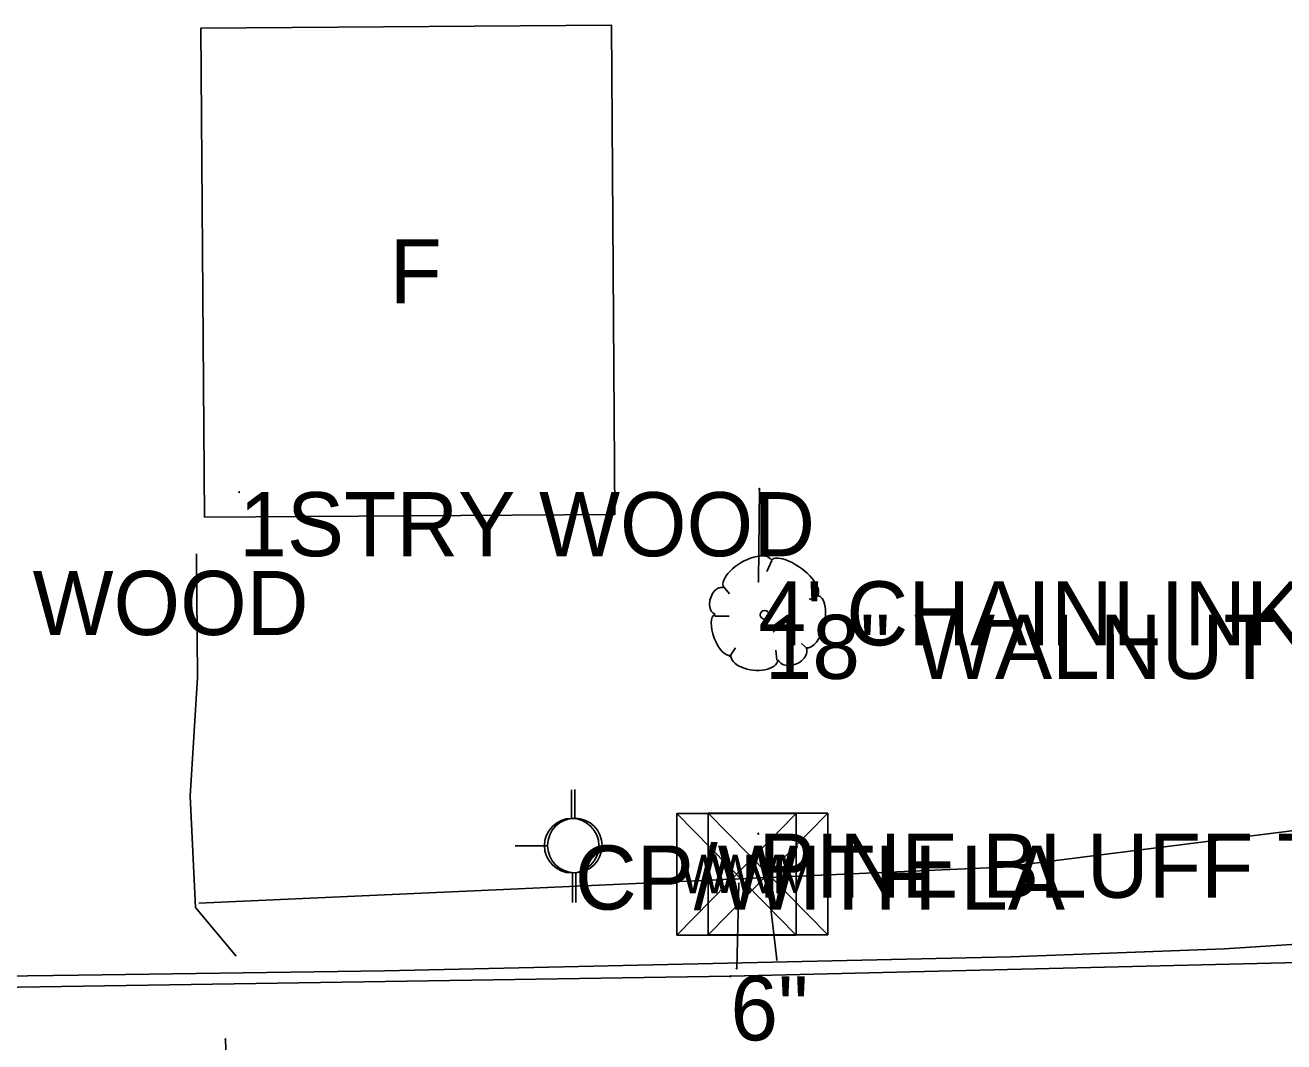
# Model space of a CAD drawing. Extents: x 1304270 to 1306561, y 1876019 to 1876752.
# Drawn here: x 1305717.8 to 1305816.1, y 1876418.6 to 1876497.9 of the extents above; entities that cross this region are included whole.
import ezdxf

# ---------------------------------------------------------------- set-up
doc = ezdxf.new("R2010")
doc.units = 0
for name, color, linetype in [('S_BUILDING', 7, 'Continuous'), ('S_BUILDING_ANNOT', 7, 'Continuous'), ('S_DRIVEWAY', 7, 'Continuous'), ('S_EDGE_PAVEMENT', 7, 'Continuous'), ('S_FENCE', 7, 'Continuous'), ('S_FENCE_ANNOT', 7, 'Continuous'), ('S_MISC_STRUCTURES_ANNOT', 7, 'Continuous'), ('S_MSC_PT_SYM', 7, 'Continuous'), ('S_SHOULDER', 7, 'Continuous'), ('S_STR_PT_SYM', 7, 'Continuous'), ('S_TREE', 7, 'Continuous'), ('S_TREE_ANNOT', 7, 'Continuous'), ('S_UTILITY_POLE', 7, 'Continuous'), ('S_UTILITY_POLE_ANNOT', 7, 'Continuous'), ('S_UTL_PT_SYM', 7, 'Continuous'), ('S_WATER_UTILITIES', 7, 'Continuous'), ('S_WATER_UTILITIES_ANNOT', 7, 'Continuous')]:
    doc.layers.add(name, color=color, linetype=linetype)

msp = doc.modelspace()

# ---------------------------------------------------------------- linework, layer by layer
at = {"layer": 'S_BUILDING'}
msp.add_lwpolyline([(1305731.787, 1876459.522), (1305731.52, 1876497.69), (1305763.568, 1876497.915), (1305763.835, 1876459.747)], close=True, dxfattribs=at)
at = {"layer": 'S_DRIVEWAY'}
msp.add_lwpolyline([(1305731.158, 1876456.665), (1305731.238, 1876447.016), (1305730.683, 1876437.757), (1305731.088, 1876429.064), (1305734.272, 1876425.27)], dxfattribs=at)
at = {"layer": 'S_EDGE_PAVEMENT'}
msp.add_lwpolyline([(1305650.553, 1876423.213), (1305674.323, 1876423.347), (1305698.094, 1876423.481), (1305721.971, 1876423.799), (1305745.849, 1876424.117), (1305770.295, 1876424.671), (1305794.741, 1876425.225), (1305811.419, 1876425.847), (1305825.074, 1876426.721), (1305843.965, 1876426.778), (1305860.029, 1876426.977), (1305876.093, 1876427.175), (1305883.239, 1876427.589), (1305898.065, 1876427.364), (1305904.047, 1876427.054), (1305918.225, 1876426.762), (1305933.321, 1876426.775)], dxfattribs=at)
at = {"layer": 'S_FENCE'}
msp.add_line((1305775.045, 1876454.521), (1305775.108, 1876461.735), dxfattribs=at)
msp.add_lwpolyline([(1305775.045, 1876454.521), (1305775.108, 1876461.735)], dxfattribs=at)
msp.add_lwpolyline([(1305775.045, 1876454.521), (1305775.108, 1876461.735)], dxfattribs=at)
at = {"layer": 'S_MSC_PT_SYM'}
for points in [[(1305775.108, 1876461.735), (1305775.108, 1876461.785), (1305775.108, 1876461.735), (1305775.058, 1876461.735), (1305775.108, 1876461.735), (1305775.108, 1876461.685), (1305775.108, 1876461.735), (1305775.158, 1876461.735)], [(1305775.045, 1876454.521), (1305775.045, 1876454.571), (1305775.045, 1876454.521), (1305774.995, 1876454.521), (1305775.045, 1876454.521), (1305775.045, 1876454.471), (1305775.045, 1876454.521), (1305775.095, 1876454.521)], [(1305775.032, 1876434.828), (1305775.032, 1876434.878), (1305775.032, 1876434.828), (1305774.982, 1876434.828), (1305775.032, 1876434.828), (1305775.032, 1876434.778), (1305775.032, 1876434.828), (1305775.082, 1876434.828)]]:
    msp.add_lwpolyline(points, dxfattribs=at)
at = {"layer": 'S_SHOULDER'}
msp.add_lwpolyline([(1305731.365, 1876429.405), (1305755.145, 1876430.481), (1305774.628, 1876431.347), (1305794.112, 1876432.214), (1305818.312, 1876435.261), (1305824.037, 1876438.54)], dxfattribs=at)
at = {"layer": 'S_STR_PT_SYM'}
msp.add_lwpolyline([(1305734.507, 1876461.478), (1305734.507, 1876461.528), (1305734.507, 1876461.478), (1305734.457, 1876461.478), (1305734.507, 1876461.478), (1305734.507, 1876461.428), (1305734.507, 1876461.478), (1305734.557, 1876461.478)], dxfattribs=at)
at = {"layer": 'S_TREE'}
for p, q in [((1305776.083, 1876456.152), (1305775.696, 1876455.299)), ((1305772.286, 1876454.137), (1305772.789, 1876453.556)), ((1305779.648, 1876453.362), (1305778.989, 1876453.091)), ((1305771.627, 1876451.812), (1305772.751, 1876451.812)), ((1305778.873, 1876449.254), (1305778.408, 1876449.681)), ((1305772.789, 1876448.634), (1305773.254, 1876449.332)), ((1305776.471, 1876448.363), (1305776.393, 1876449.138))]:
    msp.add_line(p, q, dxfattribs=at)
msp.add_circle((1305775.525, 1876451.906), 0.341, dxfattribs=at)
for centre, major_axis, ratio, start_param, end_param in [((1305774.189, 1876455.109), (1.857, 1.085), 0.471018, 0, 3.141593), ((1305777.844, 1876454.785), (-1.813, 1.36), 0.405113, 3.141593, 6.283186), ((1305771.954, 1876452.994), (0.305, 1.027), 0.646762, 0, 3.141593), ((1305779.199, 1876451.377), (0.458, 2.04), 0.482994, 3.141593, 6.283185), ((1305772.26, 1876450.344), (-0.611, 1.596), 0.420543, 6.283185, 9.424777), ((1305774.72, 1876448.563), (-1.832, 0.194), 0.529943, 0, 3.141593), ((1305777.677, 1876448.856), (1.092, 0.462), 0.711534, 3.141592, 6.283185)]:
    msp.add_ellipse(centre, major_axis=major_axis, ratio=ratio, start_param=start_param, end_param=end_param, dxfattribs=at)
at = {"layer": 'S_UTILITY_POLE'}
for p, q in [((1305760.457, 1876436.006), (1305760.457, 1876438.254)), ((1305760.702, 1876436.018), (1305760.702, 1876438.266)), ((1305758.364, 1876433.875), (1305756.039, 1876433.875)), ((1305758.609, 1876433.887), (1305756.284, 1876433.887)), ((1305760.534, 1876429.458), (1305760.534, 1876431.783)), ((1305760.779, 1876429.47), (1305760.779, 1876431.795))]:
    msp.add_line(p, q, dxfattribs=at)
for centre in [(1305760.459, 1876433.896), (1305760.704, 1876433.908)]:
    msp.add_circle(centre, 2.128, dxfattribs=at)
at = {"layer": 'S_UTL_PT_SYM'}
for points in [[(1305773.52, 1876430.931), (1305773.52, 1876430.981), (1305773.52, 1876430.931), (1305773.47, 1876430.931), (1305773.52, 1876430.931), (1305773.52, 1876430.881), (1305773.52, 1876430.931), (1305773.57, 1876430.931)], [(1305775.761, 1876430.966), (1305775.761, 1876431.016), (1305775.761, 1876430.966), (1305775.711, 1876430.966), (1305775.761, 1876430.966), (1305775.761, 1876430.916), (1305775.761, 1876430.966), (1305775.811, 1876430.966)], [(1305773.346, 1876424.316), (1305773.346, 1876424.366), (1305773.346, 1876424.316), (1305773.296, 1876424.316), (1305773.346, 1876424.316), (1305773.346, 1876424.266), (1305773.346, 1876424.316), (1305773.396, 1876424.316)], [(1305776.485, 1876425.008), (1305776.485, 1876425.058), (1305776.485, 1876425.008), (1305776.435, 1876425.008), (1305776.485, 1876425.008), (1305776.485, 1876424.958), (1305776.485, 1876425.008), (1305776.535, 1876425.008)], [(1305772.851, 1876423.704), (1305772.851, 1876423.754), (1305772.851, 1876423.704), (1305772.801, 1876423.704), (1305772.851, 1876423.704), (1305772.851, 1876423.654), (1305772.851, 1876423.704), (1305772.901, 1876423.704)], [(1305733.441, 1876418.796), (1305733.441, 1876418.846), (1305733.441, 1876418.796), (1305733.391, 1876418.796), (1305733.441, 1876418.796), (1305733.441, 1876418.746), (1305733.441, 1876418.796), (1305733.491, 1876418.796)]]:
    msp.add_lwpolyline(points, dxfattribs=at)
at = {"layer": 'S_WATER_UTILITIES'}
for p, q in [((1305768.657, 1876436.417), (1305777.995, 1876436.417)), ((1305768.657, 1876436.417), (1305768.657, 1876426.923)), ((1305768.657, 1876436.417), (1305777.995, 1876426.923)), ((1305777.995, 1876436.417), (1305768.657, 1876426.923)), ((1305771.121, 1876436.439), (1305780.46, 1876436.439)), ((1305771.121, 1876436.439), (1305771.121, 1876426.945)), ((1305771.121, 1876436.439), (1305780.46, 1876426.945)), ((1305780.46, 1876436.439), (1305771.121, 1876426.945)), ((1305777.995, 1876436.417), (1305777.995, 1876426.923)), ((1305780.46, 1876436.439), (1305780.46, 1876426.945)), ((1305776.485, 1876425.008), (1305775.761, 1876430.966)), ((1305773.52, 1876430.931), (1305773.346, 1876424.316)), ((1305768.657, 1876426.923), (1305777.995, 1876426.923)), ((1305771.121, 1876426.945), (1305780.46, 1876426.945)), ((1305874.576, 1876426.178), (1305772.851, 1876423.704)), ((1305772.851, 1876423.704), (1305687.162, 1876422.388)), ((1305733.441, 1876418.796), (1305734.264, 1876386.496))]:
    msp.add_line(p, q, dxfattribs=at)

# ---------------------------------------------------------------- texts
at = {"layer": 'S_BUILDING_ANNOT'}
for s, p in [('F', (1305746.24, 1876476.218)), ('1STRY WOOD', (1305734.507, 1876456.478)), ('1STRY WOOD', (1305694.972, 1876450.334))]:
    msp.add_text(s, height=5, dxfattribs=at).set_placement(p)
at = {"layer": 'S_FENCE_ANNOT'}
msp.add_text("4' CHAINLINK/MTL POST", height=5, dxfattribs=at).set_placement((1305775.045, 1876449.521))
at = {"layer": 'S_MISC_STRUCTURES_ANNOT'}
msp.add_text('PINE BLUFF TRANSIT/BUS ST STOP', height=5, dxfattribs=at).set_placement((1305775.032, 1876429.828))
at = {"layer": 'S_TREE_ANNOT'}
msp.add_text('18" WALNUT', height=5, dxfattribs=at).set_placement((1305775.525, 1876446.907))
at = {"layer": 'S_UTILITY_POLE_ANNOT'}
msp.add_text('CP/WITH LA', height=5, dxfattribs=at).set_placement((1305760.704, 1876428.908))
at = {"layer": 'S_WATER_UTILITIES'}
for p in [(1305768.862, 1876430.183), (1305771.326, 1876430.205)]:
    msp.add_text('W M', height=3, rotation=360, dxfattribs=at).set_placement(p)
at = {"layer": 'S_WATER_UTILITIES_ANNOT'}
msp.add_text('6"', height=5, dxfattribs=at).set_placement((1305772.851, 1876418.704))

doc.saveas('drawing.dxf')
